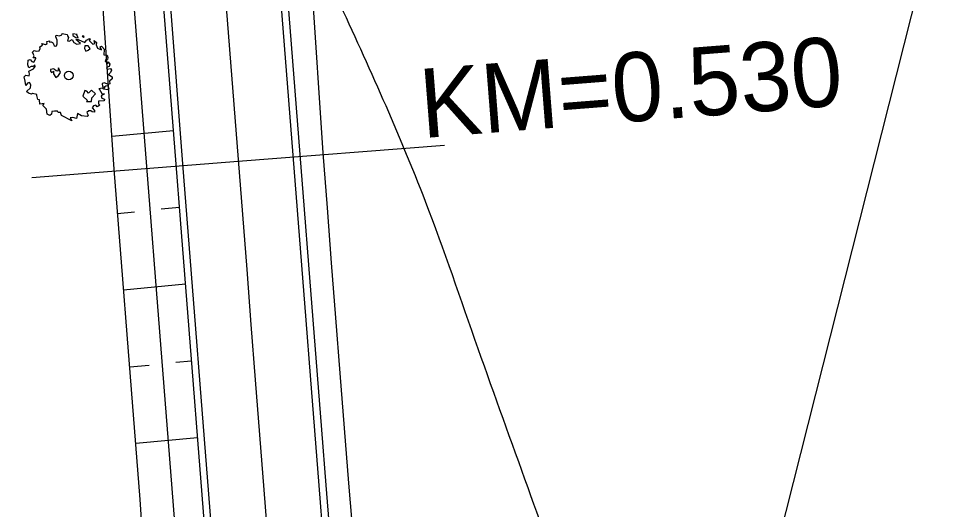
# Model space of a CAD drawing. Extents: x -477701 to -476785, y -1116511 to -1115314.
# Drawn here: x -477395.02 to -477361.35, y -1115770.83 to -1115753.07 of the extents above; entities that cross this region are included whole.
import ezdxf

# ---------------------------------------------------------------- set-up
doc = ezdxf.new("R2010")
doc.units = 0
for name, color, linetype in [('hrana_P', 7, 'Continuous'), ('hrana_R', 7, 'Continuous'), ('IP_RBK', 7, 'Continuous'), ('POLYGONY_SITUACE_PF', 7, 'Continuous'), ('POLYGONY_SITUACE_PF_POPISY', 7, 'Continuous'), ('svahování', 7, 'Continuous'), ('SVK_STAT', 7, 'Continuous'), ('Vrstevnice_vedlejsi', 7, 'Continuous')]:
    doc.layers.add(name, color=color, linetype=linetype)

msp = doc.modelspace()

# ---------------------------------------------------------------- linework, layer by layer
at = {"layer": 'hrana_P'}
for points in [[(-477383.991, -1115757.919), (-477384.384, -1115751.932)], [(-477391.557, -1115758.514), (-477391.972, -1115752.528)], [(-477383.838, -1115759.914), (-477383.991, -1115757.919)], [(-477391.402, -1115760.508), (-477391.557, -1115758.514)], [(-477383.685, -1115761.908), (-477383.838, -1115759.914)], [(-477391.247, -1115762.502), (-477391.402, -1115760.508)], [(-477383.532, -1115763.902), (-477383.685, -1115761.908)], [(-477391.091, -1115764.496), (-477391.247, -1115762.502)], [(-477383.378, -1115765.896), (-477383.532, -1115763.902)], [(-477390.93, -1115766.489), (-477391.091, -1115764.496)], [(-477383.222, -1115767.89), (-477383.378, -1115765.896)], [(-477390.77, -1115768.483), (-477390.93, -1115766.489)], [(-477383.058, -1115769.883), (-477383.222, -1115767.89)], [(-477390.623, -1115770.477), (-477390.77, -1115768.483)], [(-477382.893, -1115771.876), (-477383.058, -1115769.883)], [(-477390.486, -1115772.473), (-477390.623, -1115770.477)]]:
    msp.add_lwpolyline(points, dxfattribs=at)
at = {"layer": 'hrana_R'}
for p, q in [((-477385.301, -1115752.004), (-477384.831, -1115757.985)), ((-477384.831, -1115757.985), (-477384.674, -1115759.979)), ((-477384.674, -1115759.979), (-477384.517, -1115761.973)), ((-477384.517, -1115761.973), (-477384.361, -1115763.967)), ((-477384.361, -1115763.967), (-477384.204, -1115765.961)), ((-477384.204, -1115765.961), (-477384.047, -1115767.955)), ((-477384.047, -1115767.955), (-477383.891, -1115769.948)), ((-477383.891, -1115769.948), (-477383.734, -1115771.942))]:
    msp.add_line(p, q, dxfattribs=at)
for points in [[(-477387.544, -1115752.18), (-477387.074, -1115758.162)], [(-477385.08, -1115758.005), (-477385.55, -1115752.023)], [(-477387.538, -1115790.297), (-477388.182, -1115786.298), (-477388.182, -1115786.298), (-477388.336, -1115784.341), (-477388.65, -1115780.353), (-477388.806, -1115778.359), (-477388.963, -1115776.365), (-477389.12, -1115774.372), (-477389.276, -1115772.378), (-477389.59, -1115768.39), (-477389.746, -1115766.396), (-477389.903, -1115764.402), (-477390.059, -1115762.408), (-477390.216, -1115760.415), (-477390.373, -1115758.421), (-477390.843, -1115752.439)], [(-477389.317, -1115758.338), (-477389.787, -1115752.356)], [(-477389.068, -1115758.318), (-477389.537, -1115752.337)], [(-477388.911, -1115760.312), (-477389.068, -1115758.318)], [(-477387.074, -1115758.162), (-477386.917, -1115760.155)], [(-477384.923, -1115759.999), (-477385.08, -1115758.005)], [(-477389.16, -1115760.332), (-477389.317, -1115758.338)], [(-477384.767, -1115761.993), (-477384.923, -1115759.999)], [(-477389.003, -1115762.325), (-477389.16, -1115760.332)], [(-477388.754, -1115762.306), (-477388.911, -1115760.312)], [(-477386.917, -1115760.155), (-477386.76, -1115762.149)], [(-477384.61, -1115763.986), (-477384.767, -1115761.993)], [(-477388.847, -1115764.319), (-477389.003, -1115762.325)], [(-477388.598, -1115764.3), (-477388.754, -1115762.306)], [(-477386.76, -1115762.149), (-477386.604, -1115764.143)], [(-477384.453, -1115765.98), (-477384.61, -1115763.986)], [(-477388.69, -1115766.313), (-477388.847, -1115764.319)], [(-477388.441, -1115766.294), (-477388.598, -1115764.3)], [(-477386.604, -1115764.143), (-477386.447, -1115766.137)], [(-477384.297, -1115767.974), (-477384.453, -1115765.98)], [(-477388.534, -1115768.307), (-477388.69, -1115766.313)], [(-477388.284, -1115768.287), (-477388.441, -1115766.294)], [(-477386.447, -1115766.137), (-477386.29, -1115768.131)], [(-477384.14, -1115769.968), (-477384.297, -1115767.974)], [(-477388.377, -1115770.301), (-477388.534, -1115768.307)], [(-477388.128, -1115770.281), (-477388.284, -1115768.287)], [(-477386.29, -1115768.131), (-477386.134, -1115770.125)], [(-477383.983, -1115771.962), (-477384.14, -1115769.968)], [(-477388.22, -1115772.295), (-477388.377, -1115770.301)], [(-477387.971, -1115772.275), (-477388.128, -1115770.281)], [(-477386.134, -1115770.125), (-477385.977, -1115772.119)]]:
    msp.add_lwpolyline(points, dxfattribs=at)
at = {"layer": 'IP_RBK'}
for points in [[(-477392.288, -1115753.863), (-477392.193, -1115753.936), (-477392.215, -1115754.019), (-477392.157, -1115754.131), (-477392.022, -1115754.193), (-477392.065, -1115754.083), (-477392.015, -1115754.068), (-477391.9, -1115754.192), (-477391.922, -1115754.185), (-477391.931, -1115754.374), (-477391.814, -1115754.388), (-477391.789, -1115754.47), (-477391.804, -1115754.546), (-477391.871, -1115754.562), (-477391.889, -1115754.607), (-477391.792, -1115754.705), (-477391.779, -1115754.626), (-477391.719, -1115754.717), (-477391.743, -1115754.803), (-477391.841, -1115754.836), (-477391.811, -1115754.896), (-477391.687, -1115754.869), (-477391.652, -1115754.929), (-477391.69, -1115755.016), (-477391.765, -1115755.089), (-477391.629, -1115755.172), (-477391.631, -1115755.25), (-477391.723, -1115755.333), (-477391.713, -1115755.432), (-477391.782, -1115755.448), (-477391.905, -1115755.389), (-477391.997, -1115755.42), (-477391.981, -1115755.522), (-477391.894, -1115755.576), (-477391.901, -1115755.522), (-477391.858, -1115755.498), (-477391.8, -1115755.487), (-477391.753, -1115755.585), (-477391.795, -1115755.642), (-477391.939, -1115755.622), (-477391.989, -1115755.59), (-477392.112, -1115755.607), (-477392.099, -1115755.613), (-477392.009, -1115755.772), (-477391.904, -1115755.786), (-477392.025, -1115755.865), (-477392.001, -1115755.942), (-477391.915, -1115755.978), (-477391.917, -1115756.041), (-477392.126, -1115756.051), (-477392.131, -1115756.154), (-477392.073, -1115756.203), (-477392.177, -1115756.263), (-477392.221, -1115756.199), (-477392.309, -1115756.219), (-477392.361, -1115756.298), (-477392.27, -1115756.393), (-477392.269, -1115756.449), (-477392.356, -1115756.436), (-477392.401, -1115756.406), (-477392.478, -1115756.41), (-477392.547, -1115756.463), (-477392.498, -1115756.565), (-477392.54, -1115756.604), (-477392.739, -1115756.583), (-477392.886, -1115756.504), (-477392.924, -1115756.678), (-477393.057, -1115756.642), (-477393.151, -1115756.653), (-477393.092, -1115756.761), (-477393.462, -1115756.569), (-477393.506, -1115756.465), (-477393.589, -1115756.461), (-477393.607, -1115756.413), (-477393.723, -1115756.411), (-477393.811, -1115756.428), (-477393.829, -1115756.529), (-477393.885, -1115756.574), (-477393.985, -1115756.522), (-477394.005, -1115756.34), (-477394.139, -1115756.211), (-477394.1, -1115756.139), (-477394.257, -1115756.168), (-477394.268, -1115756.011), (-477394.324, -1115755.993), (-477394.365, -1115755.849), (-477394.365, -1115755.815), (-477394.513, -1115755.775), (-477394.555, -1115755.8), (-477394.657, -1115755.762), (-477394.737, -1115755.711), (-477394.586, -1115755.576), (-477394.582, -1115755.469), (-477394.626, -1115755.378), (-477394.695, -1115755.4), (-477394.764, -1115755.482), (-477394.784, -1115755.329), (-477394.822, -1115755.171), (-477394.76, -1115755.115), (-477394.638, -1115755.141), (-477394.626, -1115755.062), (-477394.647, -1115754.965), (-477394.482, -1115754.88), (-477394.419, -1115754.806), (-477394.43, -1115754.746), (-477394.493, -1115754.795), (-477394.566, -1115754.795), (-477394.653, -1115754.849), (-477394.687, -1115754.737), (-477394.678, -1115754.575), (-477394.601, -1115754.544), (-477394.535, -1115754.622), (-477394.465, -1115754.647), (-477394.399, -1115754.512), (-477394.393, -1115754.489), (-477394.492, -1115754.488), (-477394.455, -1115754.413), (-477394.483, -1115754.365), (-477394.511, -1115754.282), (-477394.453, -1115754.216), (-477394.387, -1115754.245), (-477394.273, -1115754.234), (-477394.244, -1115754.145), (-477394.256, -1115754.09), (-477394.154, -1115754.034), (-477394.18, -1115753.974), (-477394.049, -1115754.001), (-477393.99, -1115753.968), (-477393.993, -1115753.901), (-477393.906, -1115753.872), (-477393.898, -1115753.917), (-477393.845, -1115753.913), (-477393.789, -1115753.93), (-477393.767, -1115753.955), (-477393.758, -1115753.997), (-477393.73, -1115754.036), (-477393.696, -1115754.062), (-477393.642, -1115754.047), (-477393.619, -1115753.983), (-477393.618, -1115753.842), (-477393.666, -1115753.732), (-477393.66, -1115753.665), (-477393.543, -1115753.685), (-477393.46, -1115753.656), (-477393.44, -1115753.606), (-477393.265, -1115753.646), (-477393.251, -1115753.689), (-477393.211, -1115753.75), (-477393.246, -1115753.877), (-477393.183, -1115753.882), (-477393.083, -1115753.826), (-477393.02, -1115753.927), (-477392.914, -1115753.997), (-477392.784, -1115753.97), (-477392.947, -1115753.827), (-477392.86, -1115753.819), (-477392.618, -1115753.933), (-477392.566, -1115753.846), (-477392.458, -1115753.782), (-477392.429, -1115753.795), (-477392.459, -1115753.861), (-477392.326, -1115753.992), (-477392.265, -1115753.964)], [(-477393.057, -1115753.676), (-477392.943, -1115753.748), (-477392.869, -1115753.758), (-477392.917, -1115753.659), (-477392.896, -1115753.643), (-477393.055, -1115753.621)], [(-477392.72, -1115753.697), (-477392.671, -1115753.748), (-477392.641, -1115753.724), (-477392.656, -1115753.702)], [(-477392.62, -1115754.048), (-477392.637, -1115754.148), (-477392.587, -1115754.245), (-477392.499, -1115754.212), (-477392.428, -1115754.145), (-477392.501, -1115754.057)], [(-477393.758, -1115754.972), (-477393.758, -1115755.063), (-477393.676, -1115755.193), (-477393.579, -1115755.131), (-477393.497, -1115755.018), (-477393.575, -1115754.852), (-477393.595, -1115754.965), (-477393.661, -1115754.953), (-477393.722, -1115754.908), (-477393.749, -1115754.889), (-477393.869, -1115754.903), (-477393.862, -1115754.964), (-477393.83, -1115755.012), (-477393.783, -1115754.993)], [(-477392.624, -1115755.667), (-477392.697, -1115755.877), (-477392.53, -1115756.032), (-477392.562, -1115756.066), (-477392.376, -1115756.07), (-477392.372, -1115755.929), (-477392.238, -1115755.787), (-477392.381, -1115755.653), (-477392.483, -1115755.762), (-477392.549, -1115755.699)]]:
    msp.add_lwpolyline(points, close=True, dxfattribs=at)
msp.add_circle((-477393.205, -1115755.125), 0.158, dxfattribs=at)
at = {"layer": 'POLYGONY_SITUACE_PF'}
msp.add_lwpolyline([(-477394.545, -1115758.817), (-477387.068, -1115758.23), (-477379.591, -1115757.642)], dxfattribs=at)
at = {"layer": 'svahování'}
for points in [[(-477389.412, -1115757.124), (-477391.639, -1115757.335)], [(-477389.412, -1115757.124), (-477391.639, -1115757.335)], [(-477389.412, -1115757.124), (-477391.639, -1115757.335)], [(-477389.194, -1115759.902), (-477389.857, -1115759.965)], [(-477389.194, -1115759.902), (-477389.857, -1115759.965)], [(-477389.194, -1115759.902), (-477389.857, -1115759.965)], [(-477391.433, -1115760.115), (-477390.819, -1115760.056)], [(-477391.433, -1115760.115), (-477390.819, -1115760.056)], [(-477391.433, -1115760.115), (-477390.819, -1115760.056)], [(-477388.975, -1115762.681), (-477391.216, -1115762.893)], [(-477388.975, -1115762.681), (-477391.216, -1115762.893)], [(-477388.975, -1115762.681), (-477391.216, -1115762.893)], [(-477390.996, -1115765.671), (-477390.293, -1115765.604)], [(-477390.996, -1115765.671), (-477390.293, -1115765.604)], [(-477390.996, -1115765.671), (-477390.293, -1115765.604)], [(-477388.757, -1115765.459), (-477389.331, -1115765.513)], [(-477388.757, -1115765.459), (-477389.331, -1115765.513)], [(-477388.757, -1115765.459), (-477389.331, -1115765.513)], [(-477388.539, -1115768.237), (-477390.773, -1115768.449)], [(-477388.539, -1115768.237), (-477390.773, -1115768.449)], [(-477388.539, -1115768.237), (-477390.773, -1115768.449)]]:
    msp.add_lwpolyline(points, dxfattribs=at)
at = {"layer": 'SVK_STAT'}
msp.add_lwpolyline([(-477374.289, -1115790.361), (-477368.016, -1115774.06), (-477361.35, -1115747.71), (-477353.906, -1115725.94), (-477352.679, -1115715.642), (-477354.67, -1115710.782), (-477360.527, -1115707.826), (-477373.875, -1115703.455), (-477387.183, -1115700.691), (-477392.642, -1115700.158), (-477393.082, -1115698.805), (-477390.172, -1115692.166), (-477386.479, -1115677.608), (-477384.394, -1115660.299), (-477383.557, -1115651.168), (-477382.283, -1115647.465), (-477379.37, -1115642.174), (-477377.272, -1115640.926), (-477373.055, -1115640.159), (-477356.644, -1115643.459), (-477334.727, -1115648.433)], dxfattribs=at)
at = {"layer": 'Vrstevnice_vedlejsi'}
for points in [[(-477535.93, -1115532.82), (-477534.231, -1115534.826), (-477529.55, -1115540.603), (-477524.775, -1115546.882), (-477521.239, -1115551.827), (-477518.943, -1115555.44), (-477517.886, -1115557.72), (-477517.005, -1115559.768), (-477516.301, -1115561.585), (-477515.773, -1115563.17), (-477514.249, -1115568.143), (-477511.731, -1115576.504), (-477508.218, -1115588.252), (-477503.131, -1115599.263), (-477496.47, -1115609.538), (-477488.235, -1115619.076), (-477482.234, -1115626.134), (-477478.468, -1115630.712), (-477476.937, -1115632.811), (-477475.949, -1115634.309), (-477475.506, -1115635.207), (-477475.606, -1115635.504), (-477475.009, -1115636.168), (-477473.714, -1115637.2), (-477471.722, -1115638.6), (-477467.091, -1115642.447), (-477459.82, -1115648.74), (-477449.91, -1115657.48), (-477441.655, -1115664.837), (-477435.056, -1115670.813), (-477430.112, -1115675.407), (-477426.12, -1115679.408), (-477423.08, -1115682.818), (-477420.993, -1115685.636), (-477418.264, -1115689.357), (-477414.894, -1115693.981), (-477410.881, -1115699.507), (-477407.419, -1115704.78), (-477404.507, -1115709.801), (-477402.145, -1115714.569), (-477400.568, -1115717.748), (-477399.774, -1115719.338), (-477399.764, -1115719.338), (-477399.751, -1115719.361), (-477399.735, -1115719.406), (-477399.716, -1115719.475), (-477399.696, -1115719.545), (-477399.675, -1115719.618), (-477399.654, -1115719.693), (-477399.629, -1115719.768), (-477399.599, -1115719.845), (-477399.566, -1115719.922), (-477399.526, -1115720.024), (-477399.48, -1115720.149), (-477399.428, -1115720.299), (-477397.485, -1115724.164), (-477393.652, -1115731.746), (-477387.928, -1115743.044), (-477383.476, -1115752.353), (-477380.296, -1115759.674), (-477378.386, -1115765.008), (-477376.582, -1115770.037), (-477374.882, -1115774.763), (-477373.286, -1115779.185), (-477372.202, -1115782.353), (-477371.628, -1115784.267), (-477371.566, -1115784.927), (-477371.519, -1115785.601), (-477371.488, -1115786.291), (-477371.473, -1115786.997), (-477371.503, -1115787.551), (-477371.579, -1115787.953), (-477371.701, -1115788.205), (-477371.905, -1115788.793), (-477372.19, -1115789.717), (-477372.558, -1115790.978), (-477373.011, -1115792.65), (-477373.549, -1115794.733), (-477374.173, -1115797.226), (-477374.607, -1115798.989), (-477374.851, -1115800.019), (-477374.905, -1115800.319), (-477374.939, -1115800.599), (-477374.955, -1115800.858)], [(-477287.632, -1116051.539), (-477286.32, -1116047.536), (-477285.638, -1116044.105), (-477285.587, -1116041.246), (-477286.167, -1116038.959), (-477287.659, -1116036.397), (-477290.063, -1116033.561), (-477293.379, -1116030.449), (-477295.283, -1116025.963), (-477295.775, -1116020.104), (-477294.854, -1116012.871), (-477293.825, -1116007.495), (-477292.688, -1116003.976), (-477291.442, -1116002.315), (-477290.445, -1115998.859), (-477289.699, -1115993.611), (-477289.202, -1115986.569), (-477288.676, -1115980.878), (-477288.121, -1115976.537), (-477287.537, -1115973.548), (-477287.201, -1115971.521), (-477287.115, -1115970.456), (-477287.276, -1115970.354), (-477288.335, -1115969.099), (-477290.29, -1115966.689), (-477293.142, -1115963.125), (-477296.708, -1115959.125), (-477300.986, -1115954.688), (-477305.978, -1115949.815), (-477309.475, -1115946.392), (-477311.478, -1115944.42), (-477311.987, -1115943.899), (-477313.16, -1115942.38), (-477314.997, -1115939.862), (-477317.498, -1115936.346), (-477320.422, -1115932.577), (-477323.768, -1115928.554), (-477327.536, -1115924.277), (-477331.317, -1115918.9), (-477335.113, -1115912.423), (-477338.922, -1115904.846), (-477342.49, -1115897.876), (-477345.815, -1115891.512), (-477348.9, -1115885.756), (-477351.846, -1115880.306), (-477354.656, -1115875.16), (-477357.328, -1115870.321), (-477360.247, -1115865.399), (-477363.413, -1115860.395), (-477366.825, -1115855.308), (-477369.7, -1115850.782), (-477372.037, -1115846.815), (-477373.837, -1115843.407), (-477376.016, -1115839.798), (-477378.575, -1115835.985), (-477381.514, -1115831.971), (-477383.772, -1115828.71), (-477385.347, -1115826.203), (-477386.24, -1115824.45), (-477387.833, -1115820.914), (-477390.124, -1115815.596), (-477393.114, -1115808.495), (-477395.102, -1115803.67), (-477396.086, -1115801.12), (-477396.068, -1115800.846), (-477396.049, -1115800.554), (-477396.029, -1115800.243), (-477396.007, -1115799.914), (-477396.014, -1115799.611), (-477396.048, -1115799.335), (-477396.111, -1115799.086), (-477396.578, -1115797.601), (-477397.449, -1115794.879), (-477398.725, -1115790.921), (-477400.833, -1115785.286), (-477403.776, -1115777.975), (-477407.552, -1115768.988), (-477412.65, -1115759.156), (-477419.071, -1115748.481), (-477426.814, -1115736.962), (-477432.395, -1115728.678), (-477435.814, -1115723.629), (-477437.071, -1115721.814), (-477437.943, -1115720.536), (-477438.43, -1115719.794), (-477438.532, -1115719.589), (-477438.752, -1115719.242), (-477439.089, -1115718.756), (-477439.545, -1115718.129), (-477443.189, -1115713.546), (-477450.023, -1115705.007), (-477460.046, -1115692.512), (-477467.831, -1115683.216), (-477473.377, -1115677.119), (-477476.685, -1115674.221), (-477481.13, -1115671.048), (-477486.712, -1115667.599)], [(-477374.578, -1115696.895), (-477373.99, -1115698.54), (-477373.592, -1115699.926), (-477373.385, -1115701.054), (-477373.369, -1115701.922), (-477373.348, -1115702.539), (-477373.32, -1115702.904), (-477373.287, -1115703.017), (-477373.273, -1115703.149), (-477373.277, -1115703.299), (-477373.299, -1115703.467), (-477373.235, -1115703.727), (-477373.085, -1115704.078), (-477372.848, -1115704.521), (-477371.973, -1115706.486), (-477370.46, -1115709.975), (-477368.309, -1115714.988), (-477366.274, -1115720.038), (-477364.355, -1115725.125), (-477362.552, -1115730.251), (-477361.204, -1115734.416), (-477360.312, -1115737.623), (-477359.875, -1115739.87), (-477359.32, -1115742.334), (-477358.649, -1115745.015), (-477357.861, -1115747.913), (-477357.364, -1115750.107), (-477357.16, -1115751.597), (-477357.247, -1115752.382), (-477357.352, -1115753.597), (-477357.474, -1115755.241), (-477357.614, -1115757.315), (-477357.665, -1115758.846), (-477357.629, -1115759.835), (-477357.504, -1115760.282), (-477357.238, -1115760.772), (-477356.83, -1115761.304), (-477356.28, -1115761.88), (-477355.619, -1115762.282), (-477354.846, -1115762.511), (-477353.961, -1115762.567), (-477353.363, -1115762.954), (-477353.05, -1115763.672), (-477353.023, -1115764.72), (-477353.062, -1115766.083), (-477353.167, -1115767.761), (-477353.338, -1115769.754), (-477353.616, -1115772.773), (-477354.003, -1115776.82), (-477354.364, -1115780.527)], [(-477337.266, -1115946.887), (-477348.633, -1115933.773), (-477356.25, -1115924.996), (-477360.116, -1115920.556), (-477360.231, -1115920.451), (-477360.332, -1115920.343), (-477360.417, -1115920.231), (-477360.487, -1115920.116), (-477362.086, -1115917.208), (-477365.214, -1115911.509), (-477369.87, -1115903.018), (-477373.961, -1115895.74), (-477377.487, -1115889.676), (-477380.447, -1115884.825), (-477383.162, -1115880.486), (-477385.631, -1115876.66), (-477387.854, -1115873.346), (-477390.44, -1115869.048), (-477393.387, -1115863.766), (-477396.696, -1115857.501), (-477399.966, -1115852.076), (-477403.196, -1115847.491), (-477406.387, -1115843.745), (-477409.557, -1115839.142), (-477412.706, -1115833.68), (-477415.833, -1115827.36), (-477419.365, -1115820.809), (-477423.302, -1115814.027), (-477427.644, -1115807.013), (-477431.429, -1115800.502), (-477434.657, -1115794.492), (-477437.328, -1115788.984), (-477440.163, -1115783.757), (-477443.16, -1115778.81), (-477446.319, -1115774.144), (-477449.256, -1115769.981), (-477451.971, -1115766.319), (-477454.463, -1115763.16), (-477457.329, -1115759.698), (-477460.57, -1115755.933), (-477464.185, -1115751.866), (-477467.95, -1115747.267), (-477471.866, -1115742.136), (-477475.933, -1115736.472), (-477480.254, -1115731.495), (-477484.827, -1115727.205), (-477489.655, -1115723.603), (-477494.56, -1115720.054), (-477499.544, -1115716.559), (-477504.606, -1115713.117), (-477509.129, -1115709.621), (-477513.112, -1115706.071), (-477513.981, -1115705.193), (-477514.797, -1115704.267), (-477515.631, -1115703.342), (-477516.556, -1115702.467), (-477521.43, -1115700.546), (-477527.734, -1115700.309), (-477529.666, -1115700.63), (-477531.592, -1115701.045), (-477533.522, -1115701.453), (-477535.469, -1115701.756), (-477542.487, -1115702.155), (-477548.79, -1115701.506), (-477550.21, -1115701.152), (-477551.595, -1115700.671), (-477552.975, -1115700.184), (-477554.378, -1115699.809), (-477559.514, -1115699.703), (-477564.199, -1115701.187), (-477568.432, -1115704.261), (-477572.401, -1115707.717), (-477576.106, -1115711.556), (-477579.547, -1115715.778), (-477582.875, -1115719.448), (-477586.091, -1115722.567), (-477589.196, -1115725.133), (-477592.121, -1115728.755), (-477594.867, -1115733.431), (-477597.433, -1115739.162), (-477599.711, -1115744.095), (-477601.7, -1115748.229), (-477603.4, -1115751.564), (-477604.536, -1115754.357), (-477605.107, -1115756.608), (-477605.113, -1115758.317), (-477606.183, -1115762.278), (-477607.852, -1115767.203)]]:
    msp.add_spline(points, degree=3, dxfattribs=at)

# ---------------------------------------------------------------- texts
at = {"layer": 'POLYGONY_SITUACE_PF_POPISY'}
msp.add_text('KM=0.530', height=2.5, rotation=4.492, dxfattribs=at).set_placement((-477380.391, -1115757.394))

doc.saveas('drawing.dxf')
